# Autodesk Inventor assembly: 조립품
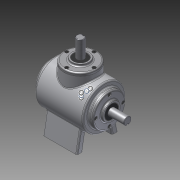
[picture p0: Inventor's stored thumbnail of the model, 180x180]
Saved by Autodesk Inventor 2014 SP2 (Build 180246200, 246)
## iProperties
Created: 2015-01
Part Number: 조립품
Document SubType Name: Assembly
Designer: 201-06
Author: 201-06
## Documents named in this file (15)
- C:\Users\201-06\Desktop\450105V1004\조립품.iam
- C:\Users\201-06\Desktop\450105V1004\본체.ipt
- C:\Users\201-06\Desktop\450105V1004\커버.ipt
- C:\Users\201-06\Desktop\450105V1004\커버2.ipt
- C:\Users\201-06\Desktop\450105V1004\메인 축.ipt
- 메인 축.ipt
- C:\Users\201-06\Desktop\450105V1004\서브 축.ipt
- 서브 축.ipt
- C:\Users\201-06\Desktop\450105V1004\메인 베벨기어.ipt
- C:\Users\201-06\Desktop\450105V1004\서브 베벨기어.ipt
- C:\Users\201-06\Desktop\450105V1004\베어링 6203.ipt
- C:\Users\201-06\Desktop\450105V1004\오일실.ipt
- C:\Users\201-06\Desktop\450105V1004\키 5x5.ipt
- C:\Users\201-06\Desktop\450105V1004\키 4x4.ipt
- C:\Users\201-06\Desktop\450105V1004\M4.ipt
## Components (12 placed, 1 different names)
1. M4:2
2. M4:4
3. M4:5
4. M4:6
5. M4:3
6. M4:7
7. M4:8
8. M4:9
9. M4:1
10. M4:10
11. M4:11
12. M4:12
